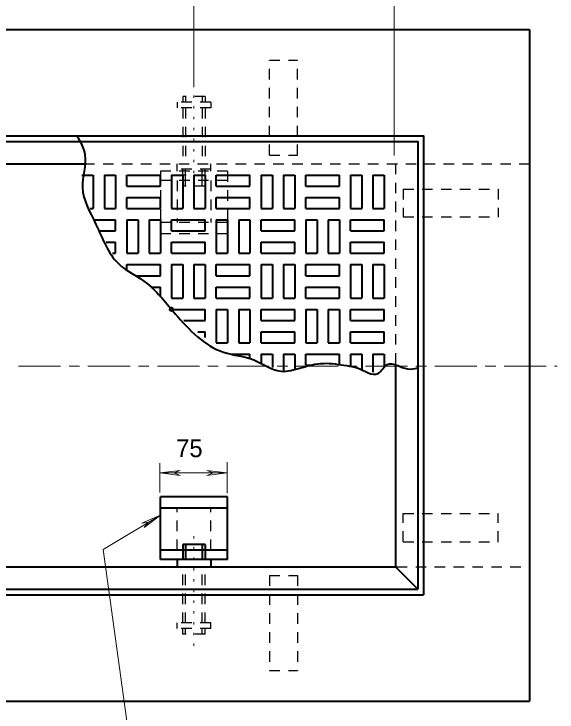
# Model space of a CAD drawing. Extents: x 312583 to 312854, y 144419 to 144597.
# Drawn here: x 312650.21 to 312673.47, y 144542.68 to 144572.55 of the extents above; entities that cross this region are included whole.
import ezdxf

# ---------------------------------------------------------------- set-up
doc = ezdxf.new("R2010")
doc.units = 0
doc.header["$LTSCALE"] = 0.3
doc.header["$PDMODE"] = 32
doc.header["$PDSIZE"] = 0.15
for name, pattern in [('DOTTED', [1.5, 0.3, -1.2]), ('LONG_DASH_SHORT_DASH', [9.9, 6, -1.2, 1.5, -1.2]), ('SHORT_DASHED', [2.7, 1.5, -1.2])]:
    doc.linetypes.add(name, pattern=pattern)
doc.layers.add('1', color=7, linetype='Continuous', lineweight=40)
doc.layers.add('2', color=7, linetype='Continuous', lineweight=13)

msp = doc.modelspace()

# ---------------------------------------------------------------- linework, layer by layer
at = {"layer": '1'}
for p, q in [((312626.2931, 144571.8954), (312672.2931, 144571.8954)), ((312672.2931, 144571.8954), (312672.2931, 144543.1454)), ((312632.0508, 144566.1454), (312653.2184, 144566.1454)), ((312653.1264, 144565.6624), (312653.6094, 144565.6624)), ((312653.6094, 144565.6624), (312653.6094, 144564.2288)), ((312654.0848, 144565.6624), (312654.0848, 144564.2288)), ((312654.0848, 144565.6624), (312654.5678, 144565.6624)), ((312654.5678, 144565.6624), (312654.5678, 144564.2288)), ((312655.0431, 144565.6624), (312656.4844, 144565.6624)), ((312655.0431, 144565.1871), (312655.0431, 144565.6624)), ((312656.4844, 144565.1871), (312656.4844, 144565.6624)), ((312656.9598, 144565.6624), (312656.9598, 144564.2288)), ((312656.9598, 144565.6624), (312657.4428, 144565.6624)), ((312657.4428, 144565.6624), (312657.4428, 144564.2288)), ((312657.9181, 144565.6624), (312657.9181, 144564.2288)), ((312657.9181, 144565.6624), (312658.4011, 144565.6624)), ((312658.4011, 144565.6624), (312658.4011, 144564.2288)), ((312658.8764, 144565.6624), (312660.3178, 144565.6624)), ((312658.8764, 144565.1871), (312658.8764, 144565.6624)), ((312660.3178, 144565.1871), (312660.3178, 144565.6624)), ((312660.7931, 144565.6624), (312660.7931, 144564.2288)), ((312660.7931, 144565.6624), (312661.2761, 144565.6624)), ((312661.2761, 144565.6624), (312661.2761, 144564.2288)), ((312661.7514, 144565.6624), (312661.7514, 144564.2288)), ((312661.7514, 144565.6624), (312662.2344, 144565.6624)), ((312662.2344, 144565.6624), (312662.2344, 144564.2288)), ((312662.7098, 144565.6624), (312664.1511, 144565.6624)), ((312662.7098, 144565.1871), (312662.7098, 144565.6624)), ((312664.1511, 144565.1871), (312664.1511, 144565.6624)), ((312664.6264, 144565.6624), (312664.6264, 144564.2288)), ((312664.6264, 144565.6624), (312665.1094, 144565.6624)), ((312665.1094, 144565.6624), (312665.1094, 144564.2288)), ((312665.5848, 144565.6624), (312665.5848, 144564.2288)), ((312665.5848, 144565.6624), (312666.0678, 144565.6624)), ((312666.0678, 144565.6624), (312666.0678, 144564.2288)), ((312655.0431, 144565.1871), (312656.4844, 144565.1871)), ((312658.8764, 144565.1871), (312660.3178, 144565.1871)), ((312662.7098, 144565.1871), (312664.1511, 144565.1871)), ((312655.0431, 144564.7041), (312656.4844, 144564.7041)), ((312655.0431, 144564.2288), (312655.0431, 144564.7041)), ((312656.4844, 144564.2288), (312656.4844, 144564.7041)), ((312658.8764, 144564.7041), (312660.3178, 144564.7041)), ((312658.8764, 144564.2288), (312658.8764, 144564.7041)), ((312660.3178, 144564.2288), (312660.3178, 144564.7041)), ((312662.7098, 144564.7041), (312664.1511, 144564.7041)), ((312662.7098, 144564.2288), (312662.7098, 144564.7041)), ((312664.1511, 144564.2288), (312664.1511, 144564.7041)), ((312653.4791, 144564.2288), (312653.6094, 144564.2288)), ((312654.0848, 144564.2288), (312654.5678, 144564.2288)), ((312655.0431, 144564.2288), (312656.4844, 144564.2288)), ((312656.9598, 144564.2288), (312657.4428, 144564.2288)), ((312657.9181, 144564.2288), (312658.4011, 144564.2288)), ((312658.8764, 144564.2288), (312660.3178, 144564.2288)), ((312660.7931, 144564.2288), (312661.2761, 144564.2288)), ((312661.7514, 144564.2288), (312662.2344, 144564.2288)), ((312662.7098, 144564.2288), (312664.1511, 144564.2288)), ((312664.6264, 144564.2288), (312665.1094, 144564.2288)), ((312665.5848, 144564.2288), (312666.0678, 144564.2288)), ((312653.6554, 144563.7458), (312654.5678, 144563.7458)), ((312654.5678, 144563.2704), (312654.5678, 144563.7458)), ((312655.0431, 144563.7458), (312655.0431, 144562.3121)), ((312655.0431, 144563.7458), (312655.5261, 144563.7458)), ((312655.5261, 144563.7458), (312655.5261, 144562.3121)), ((312656.0014, 144563.7458), (312656.0014, 144562.3121)), ((312656.0014, 144563.7458), (312656.4844, 144563.7458)), ((312656.4844, 144563.7458), (312656.4844, 144562.3121)), ((312656.9598, 144563.7458), (312658.4011, 144563.7458)), ((312656.9598, 144563.2704), (312656.9598, 144563.7458)), ((312658.4011, 144563.2704), (312658.4011, 144563.7458)), ((312658.8764, 144563.7458), (312658.8764, 144562.3121)), ((312658.8764, 144563.7458), (312659.3594, 144563.7458)), ((312659.3594, 144563.7458), (312659.3594, 144562.3121)), ((312659.8348, 144563.7458), (312659.8348, 144562.3121)), ((312659.8348, 144563.7458), (312660.3178, 144563.7458)), ((312660.3178, 144563.7458), (312660.3178, 144562.3121)), ((312660.7931, 144563.7458), (312662.2344, 144563.7458)), ((312660.7931, 144563.2704), (312660.7931, 144563.7458)), ((312662.2344, 144563.2704), (312662.2344, 144563.7458)), ((312662.7098, 144563.7458), (312662.7098, 144562.3121)), ((312662.7098, 144563.7458), (312663.1928, 144563.7458)), ((312663.1928, 144563.7458), (312663.1928, 144562.3121)), ((312663.6681, 144563.7458), (312663.6681, 144562.3121)), ((312663.6681, 144563.7458), (312664.1511, 144563.7458)), ((312664.1511, 144563.7458), (312664.1511, 144562.3121)), ((312664.6264, 144563.7458), (312666.0678, 144563.7458)), ((312664.6264, 144563.2704), (312664.6264, 144563.7458)), ((312666.0678, 144563.2704), (312666.0678, 144563.7458)), ((312653.8854, 144563.2704), (312654.5678, 144563.2704)), ((312656.9598, 144563.2704), (312658.4011, 144563.2704)), ((312660.7931, 144563.2704), (312662.2344, 144563.2704)), ((312664.6264, 144563.2704), (312666.0678, 144563.2704)), ((312654.1614, 144562.7874), (312654.5678, 144562.7874)), ((312654.5678, 144562.3121), (312654.5678, 144562.7874)), ((312656.9598, 144562.7874), (312658.4011, 144562.7874)), ((312656.9598, 144562.3121), (312656.9598, 144562.7874)), ((312658.4011, 144562.3121), (312658.4011, 144562.7874)), ((312660.7931, 144562.7874), (312662.2344, 144562.7874)), ((312660.7931, 144562.3121), (312660.7931, 144562.7874)), ((312662.2344, 144562.3121), (312662.2344, 144562.7874)), ((312664.6264, 144562.7874), (312666.0678, 144562.7874)), ((312664.6264, 144562.3121), (312664.6264, 144562.7874)), ((312666.0678, 144562.3121), (312666.0678, 144562.7874)), ((312654.4374, 144562.3121), (312654.5678, 144562.3121)), ((312655.0431, 144562.3121), (312655.5261, 144562.3121)), ((312656.0014, 144562.3121), (312656.4844, 144562.3121)), ((312656.9598, 144562.3121), (312658.4011, 144562.3121)), ((312658.8764, 144562.3121), (312659.3594, 144562.3121)), ((312659.8348, 144562.3121), (312660.3178, 144562.3121)), ((312660.7931, 144562.3121), (312662.2344, 144562.3121)), ((312662.7098, 144562.3121), (312663.1928, 144562.3121)), ((312663.6681, 144562.3121), (312664.1511, 144562.3121)), ((312664.6264, 144562.3121), (312666.0678, 144562.3121)), ((312655.0431, 144561.8291), (312656.4844, 144561.8291)), ((312655.0431, 144561.6221), (312655.0431, 144561.8291)), ((312656.4844, 144561.3538), (312656.4844, 144561.8291)), ((312656.9598, 144561.8291), (312656.9598, 144560.3954)), ((312656.9598, 144561.8291), (312657.4428, 144561.8291)), ((312657.4428, 144561.8291), (312657.4428, 144560.3954)), ((312657.9181, 144561.8291), (312657.9181, 144560.3954)), ((312657.9181, 144561.8291), (312658.4011, 144561.8291)), ((312658.4011, 144561.8291), (312658.4011, 144560.3954)), ((312658.8764, 144561.8291), (312660.3178, 144561.8291)), ((312658.8764, 144561.3538), (312658.8764, 144561.8291)), ((312660.3178, 144561.3538), (312660.3178, 144561.8291)), ((312660.7931, 144561.8291), (312660.7931, 144560.3954)), ((312660.7931, 144561.8291), (312661.2761, 144561.8291)), ((312661.2761, 144561.8291), (312661.2761, 144560.3954)), ((312661.7514, 144561.8291), (312661.7514, 144560.3954)), ((312661.7514, 144561.8291), (312662.2344, 144561.8291)), ((312662.2344, 144561.8291), (312662.2344, 144560.3954)), ((312662.7098, 144561.8291), (312664.1511, 144561.8291)), ((312662.7098, 144561.3538), (312662.7098, 144561.8291)), ((312664.1511, 144561.3538), (312664.1511, 144561.8291)), ((312664.6264, 144561.8291), (312664.6264, 144560.3954)), ((312664.6264, 144561.8291), (312665.1094, 144561.8291)), ((312665.1094, 144561.8291), (312665.1094, 144560.3954)), ((312665.5848, 144561.8291), (312665.5848, 144560.3954)), ((312665.5848, 144561.8291), (312666.0678, 144561.8291)), ((312666.0678, 144561.8291), (312666.0678, 144560.3954)), ((312655.4341, 144561.3538), (312656.4844, 144561.3538)), ((312658.8764, 144561.3538), (312660.3178, 144561.3538)), ((312662.7098, 144561.3538), (312664.1511, 144561.3538)), ((312656.0704, 144560.8708), (312656.4844, 144560.8708)), ((312656.4844, 144560.4568), (312656.4844, 144560.8708)), ((312658.8764, 144560.8708), (312660.3178, 144560.8708)), ((312658.8764, 144560.3954), (312658.8764, 144560.8708)), ((312660.3178, 144560.3954), (312660.3178, 144560.8708)), ((312662.7098, 144560.8708), (312664.1511, 144560.8708)), ((312662.7098, 144560.3954), (312662.7098, 144560.8708)), ((312664.1511, 144560.3954), (312664.1511, 144560.8708)), ((312656.9598, 144560.3954), (312657.4428, 144560.3954)), ((312657.9181, 144560.3954), (312658.4011, 144560.3954)), ((312658.8764, 144560.3954), (312660.3178, 144560.3954)), ((312660.7931, 144560.3954), (312661.2761, 144560.3954)), ((312661.7514, 144560.3954), (312662.2344, 144560.3954)), ((312662.7098, 144560.3954), (312664.1511, 144560.3954)), ((312664.6264, 144560.3954), (312665.1094, 144560.3954)), ((312665.5848, 144560.3954), (312666.0678, 144560.3954)), ((312656.9598, 144559.9124), (312658.4011, 144559.9124)), ((312658.4011, 144559.4371), (312658.4011, 144559.9124)), ((312658.8764, 144559.9124), (312658.8764, 144558.4788)), ((312658.8764, 144559.9124), (312659.3594, 144559.9124)), ((312659.3594, 144559.9124), (312659.3594, 144558.4788)), ((312659.8348, 144559.9124), (312659.8348, 144558.4788)), ((312659.8348, 144559.9124), (312660.3178, 144559.9124)), ((312660.3178, 144559.9124), (312660.3178, 144558.4788)), ((312660.7931, 144559.9124), (312662.2344, 144559.9124)), ((312660.7931, 144559.4371), (312660.7931, 144559.9124)), ((312662.2344, 144559.4371), (312662.2344, 144559.9124)), ((312662.7098, 144559.9124), (312662.7098, 144558.4788)), ((312662.7098, 144559.9124), (312663.1928, 144559.9124)), ((312663.1928, 144559.9124), (312663.1928, 144558.4788)), ((312663.6681, 144559.9124), (312663.6681, 144558.4788)), ((312663.6681, 144559.9124), (312664.1511, 144559.9124)), ((312664.1511, 144559.9124), (312664.1511, 144558.4788)), ((312664.6264, 144559.9124), (312666.0678, 144559.9124)), ((312664.6264, 144559.4371), (312664.6264, 144559.9124)), ((312666.0678, 144559.4371), (312666.0678, 144559.9124)), ((312657.4811, 144559.4371), (312658.4011, 144559.4371)), ((312660.7931, 144559.4371), (312662.2344, 144559.4371)), ((312664.6264, 144559.4371), (312666.0678, 144559.4371)), ((312658.0868, 144558.9541), (312658.4011, 144558.9541)), ((312658.4011, 144558.7088), (312658.4011, 144558.9541)), ((312660.7931, 144558.9541), (312662.2344, 144558.9541)), ((312660.7931, 144558.4788), (312660.7931, 144558.9541)), ((312662.2344, 144558.4788), (312662.2344, 144558.9541)), ((312664.6264, 144558.9541), (312666.0678, 144558.9541)), ((312664.6264, 144558.4788), (312664.6264, 144558.9541)), ((312666.0678, 144558.4788), (312666.0678, 144558.9541)), ((312658.8764, 144558.4788), (312659.3594, 144558.4788)), ((312659.8348, 144558.4788), (312660.3178, 144558.4788)), ((312660.7931, 144558.4788), (312662.2344, 144558.4788)), ((312662.7098, 144558.4788), (312663.1928, 144558.4788)), ((312663.6681, 144558.4788), (312664.1511, 144558.4788)), ((312664.6264, 144558.4788), (312666.0678, 144558.4788)), ((312659.5204, 144557.9958), (312660.3178, 144557.9958)), ((312660.3178, 144557.7888), (312660.3178, 144557.9958)), ((312660.7931, 144557.9958), (312660.7931, 144557.6201)), ((312660.7931, 144557.9958), (312661.2761, 144557.9958)), ((312661.2761, 144557.9958), (312661.2761, 144557.4208)), ((312661.7514, 144557.9958), (312661.7514, 144557.2904)), ((312661.7514, 144557.9958), (312662.2344, 144557.9958)), ((312662.2344, 144557.9958), (312662.2344, 144557.3671)), ((312662.7098, 144557.9958), (312664.1511, 144557.9958)), ((312662.7098, 144557.5204), (312662.7098, 144557.9958)), ((312664.1511, 144557.5358), (312664.1511, 144557.9958)), ((312664.6264, 144557.9958), (312664.6264, 144557.4744)), ((312664.6264, 144557.9958), (312665.1094, 144557.9958)), ((312665.1094, 144557.9958), (312665.1094, 144557.3594)), ((312665.5848, 144557.9958), (312665.5848, 144557.2291)), ((312665.5848, 144557.9958), (312666.0678, 144557.9958)), ((312666.0678, 144557.9958), (312666.0678, 144557.4284)), ((312662.7098, 144557.5204), (312663.0394, 144557.5204)), ((312666.5431, 144557.4744), (312666.5431, 144548.8954)), ((312659.3594, 144551.8854), (312656.4844, 144551.8854)), ((312656.4844, 144549.2174), (312656.4844, 144551.8854)), ((312659.3594, 144549.2174), (312659.3594, 144551.8854)), ((312659.3594, 144551.4101), (312656.4844, 144551.4101)), ((312658.4011, 144549.8538), (312657.4428, 144549.8538)), ((312657.4428, 144549.8538), (312657.4428, 144549.2174)), ((312657.5578, 144549.8538), (312657.5578, 144549.2174)), ((312658.2784, 144549.8538), (312658.2784, 144549.2174)), ((312658.4011, 144549.8538), (312658.4011, 144549.2174)), ((312659.3594, 144549.6161), (312656.4844, 144549.6161)), ((312659.3594, 144549.2174), (312656.4844, 144549.2174)), ((312657.2051, 144549.2174), (312657.2051, 144548.8954)), ((312658.6388, 144549.2174), (312658.6388, 144548.8954)), ((312632.1121, 144548.8954), (312666.5354, 144548.8954)), ((312666.5431, 144548.8954), (312667.5014, 144547.9371)), ((312631.0848, 144547.9371), (312667.5014, 144547.9371)), ((312630.8471, 144547.6994), (312667.7468, 144547.6994)), ((312626.2931, 144543.1454), (312672.2931, 144543.1454))]:
    msp.add_line(p, q, dxfattribs=at)
at = {"layer": '1', "linetype": 'SHORT_DASHED', "lineweight": 25}
for p, q in [((312661.1534, 144570.5844), (312662.3494, 144570.5844)), ((312661.1534, 144566.5134), (312661.1534, 144570.5844)), ((312662.3494, 144566.5134), (312662.3494, 144570.5844)), ((312658.6388, 144568.7828), (312657.2051, 144568.7828)), ((312657.2051, 144568.7828), (312657.2051, 144568.5374)), ((312658.4011, 144569.0204), (312657.4428, 144569.0204)), ((312657.4428, 144569.0204), (312657.4428, 144568.7828)), ((312657.5578, 144569.0204), (312657.5578, 144568.7828)), ((312658.2784, 144569.0204), (312658.2784, 144568.7828)), ((312658.4011, 144569.0204), (312658.4011, 144568.7828)), ((312658.6388, 144568.7828), (312658.6388, 144568.5374)), ((312658.6388, 144568.5374), (312657.2051, 144568.5374)), ((312657.4428, 144568.5374), (312657.4428, 144566.1454)), ((312657.5578, 144568.5374), (312657.5578, 144566.1454)), ((312658.2784, 144568.5374), (312658.2784, 144566.1454)), ((312658.4011, 144568.5374), (312658.4011, 144566.1454)), ((312661.1534, 144566.5134), (312662.3494, 144566.5134)), ((312653.2184, 144566.1454), (312672.2931, 144566.1454)), ((312657.2051, 144565.9078), (312657.2051, 144566.1454)), ((312657.2051, 144565.8234), (312657.2051, 144566.1454)), ((312658.6388, 144565.9078), (312658.6388, 144566.1454)), ((312658.6388, 144565.8234), (312658.6388, 144566.1454)), ((312666.5431, 144566.1454), (312666.5431, 144557.4744)), ((312656.4844, 144565.8234), (312656.4844, 144563.1478)), ((312659.3594, 144565.8234), (312656.4844, 144565.8234)), ((312658.6388, 144565.9078), (312657.2051, 144565.9078)), ((312657.4428, 144565.6624), (312657.4428, 144565.9078)), ((312657.4428, 144565.1871), (312657.4428, 144565.8234)), ((312657.5578, 144565.6624), (312657.5578, 144565.9078)), ((312657.5578, 144565.1871), (312657.5578, 144565.8234)), ((312658.2784, 144565.6624), (312658.2784, 144565.9078)), ((312658.2784, 144565.1871), (312658.2784, 144565.8234)), ((312658.4011, 144565.6624), (312658.4011, 144565.9078)), ((312658.4011, 144565.1871), (312658.4011, 144565.8234)), ((312659.3594, 144565.8234), (312659.3594, 144563.1478)), ((312658.4011, 144565.6624), (312657.4428, 144565.6624)), ((312659.3594, 144565.4248), (312656.4844, 144565.4248)), ((312657.2051, 144565.4248), (312657.2051, 144563.6308)), ((312658.4011, 144565.1871), (312657.4428, 144565.1871)), ((312658.6388, 144565.4248), (312658.6388, 144563.6308)), ((312666.8804, 144565.0644), (312666.8804, 144563.8684)), ((312666.8804, 144565.0644), (312670.9438, 144565.0644)), ((312670.9438, 144565.0644), (312670.9438, 144563.8684)), ((312666.8804, 144563.8684), (312670.9438, 144563.8684)), ((312659.3594, 144563.6308), (312656.4844, 144563.6308)), ((312659.3594, 144563.1478), (312656.4844, 144563.1478)), ((312657.2051, 144549.6161), (312657.2051, 144551.4101)), ((312658.6388, 144549.6161), (312658.6388, 144551.4101)), ((312666.8804, 144549.9688), (312666.8804, 144551.1724)), ((312666.8804, 144551.1724), (312670.9438, 144551.1724)), ((312670.9438, 144549.9688), (312670.9438, 144551.1724)), ((312666.8804, 144549.9688), (312670.9438, 144549.9688)), ((312657.4428, 144546.4958), (312657.4428, 144548.8954)), ((312657.5578, 144546.4958), (312657.5578, 144548.8954)), ((312658.2784, 144546.4958), (312658.2784, 144548.8954)), ((312658.4011, 144546.4958), (312658.4011, 144548.8954)), ((312666.6044, 144548.8954), (312672.2931, 144548.8954)), ((312661.1534, 144548.5274), (312662.3494, 144548.5274)), ((312661.1534, 144548.5274), (312661.1534, 144544.4564)), ((312662.3494, 144548.5274), (312662.3494, 144544.4564)), ((312658.6388, 144546.4958), (312657.2051, 144546.4958)), ((312657.2051, 144546.2581), (312657.2051, 144546.4958)), ((312658.6388, 144546.2581), (312658.6388, 144546.4958)), ((312658.6388, 144546.2581), (312657.2051, 144546.2581)), ((312657.4428, 144546.0204), (312657.4428, 144546.2581)), ((312657.5578, 144546.0204), (312657.5578, 144546.2581)), ((312658.2784, 144546.0204), (312658.2784, 144546.2581)), ((312658.4011, 144546.0204), (312658.4011, 144546.2581)), ((312658.4011, 144546.0204), (312657.4428, 144546.0204)), ((312661.1534, 144544.4564), (312662.3494, 144544.4564))]:
    msp.add_line(p, q, dxfattribs=at)
at = {"layer": '1', "linetype": 'DOTTED', "lineweight": 13}
for p, q in [((312657.9181, 144569.5264), (312657.9181, 144564.7041)), ((312657.9181, 144545.5144), (312657.9181, 144550.2524))]:
    msp.add_line(p, q, dxfattribs=at)
at = {"layer": '1'}
for points in [[(312630.8471, 144567.3414), (312667.7468, 144567.3414), (312667.7468, 144547.6994)], [(312631.0848, 144567.1038), (312667.5014, 144567.1038), (312667.5014, 144547.9371)]]:
    msp.add_lwpolyline(points, dxfattribs=at)
msp.add_spline([(312652.9118, 144567.3414), (312653.2491, 144566.5211), (312653.1494, 144565.1334), (312653.7244, 144563.5464), (312654.6828, 144561.8751), (312655.9324, 144561.0088), (312656.5534, 144560.3878), (312657.1284, 144559.7131), (312659.1908, 144558.0801), (312660.4864, 144557.7504), (312661.6364, 144557.2674), (312662.5028, 144557.4131), (312663.4611, 144557.6048), (312664.4654, 144557.5051), (312664.9024, 144557.4131), (312665.8071, 144557.1754), (312666.1981, 144557.5588), (312667.0568, 144557.3671), (312667.5014, 144557.4131)], degree=3, dxfattribs=at)
msp.add_point((312656.9598, 144559.9124), dxfattribs=at)
at = {"layer": '2'}
for p, q in [((312666.4971, 144566.4981), (312666.4971, 144577.1778)), ((312656.4614, 144552.0848), (312656.4614, 144553.3344)), ((312659.3441, 144552.0541), (312659.3441, 144553.3804)), ((312656.4614, 144552.9128), (312657.3278, 144553.0201)), ((312657.3278, 144553.0201), (312657.0518, 144552.9128)), ((312658.4778, 144553.0201), (312658.7538, 144552.9128)), ((312659.3441, 144552.9128), (312658.4778, 144553.0201)), ((312656.4614, 144552.9128), (312659.3441, 144552.9128)), ((312656.4614, 144552.9128), (312657.3278, 144552.8054)), ((312657.3278, 144552.8054), (312657.0518, 144552.9128)), ((312658.4778, 144552.8054), (312658.7538, 144552.9128)), ((312659.3441, 144552.9128), (312658.4778, 144552.8054)), ((312656.4844, 144551.1111), (312655.6871, 144550.7584)), ((312656.4844, 144551.1111), (312655.7944, 144550.5744)), ((312655.6871, 144550.7584), (312655.9784, 144550.8044)), ((312655.7944, 144550.5744), (312655.9784, 144550.8044))]:
    msp.add_line(p, q, dxfattribs=at)
at = {"layer": '2', "linetype": 'LONG_DASH_SHORT_DASH'}
msp.add_line((312650.4124, 144557.4898), (312673.4661, 144557.4898), dxfattribs=at)
at = {"layer": '2'}
for points in [[(312657.9181, 144569.5264), (312657.9181, 144574.0958), (312657.9181, 144574.4868)], [(312655.2041, 144541.1598), (312654.0311, 144549.6391), (312656.4844, 144551.1111)]]:
    msp.add_lwpolyline(points, dxfattribs=at)

# ---------------------------------------------------------------- texts
at = {"layer": '1'}
msp.add_text('75', height=0.76, dxfattribs=at).set_placement((312657.159, 144553.5905))

doc.saveas('drawing.dxf')
